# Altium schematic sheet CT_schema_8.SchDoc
size 371 x 336 mm
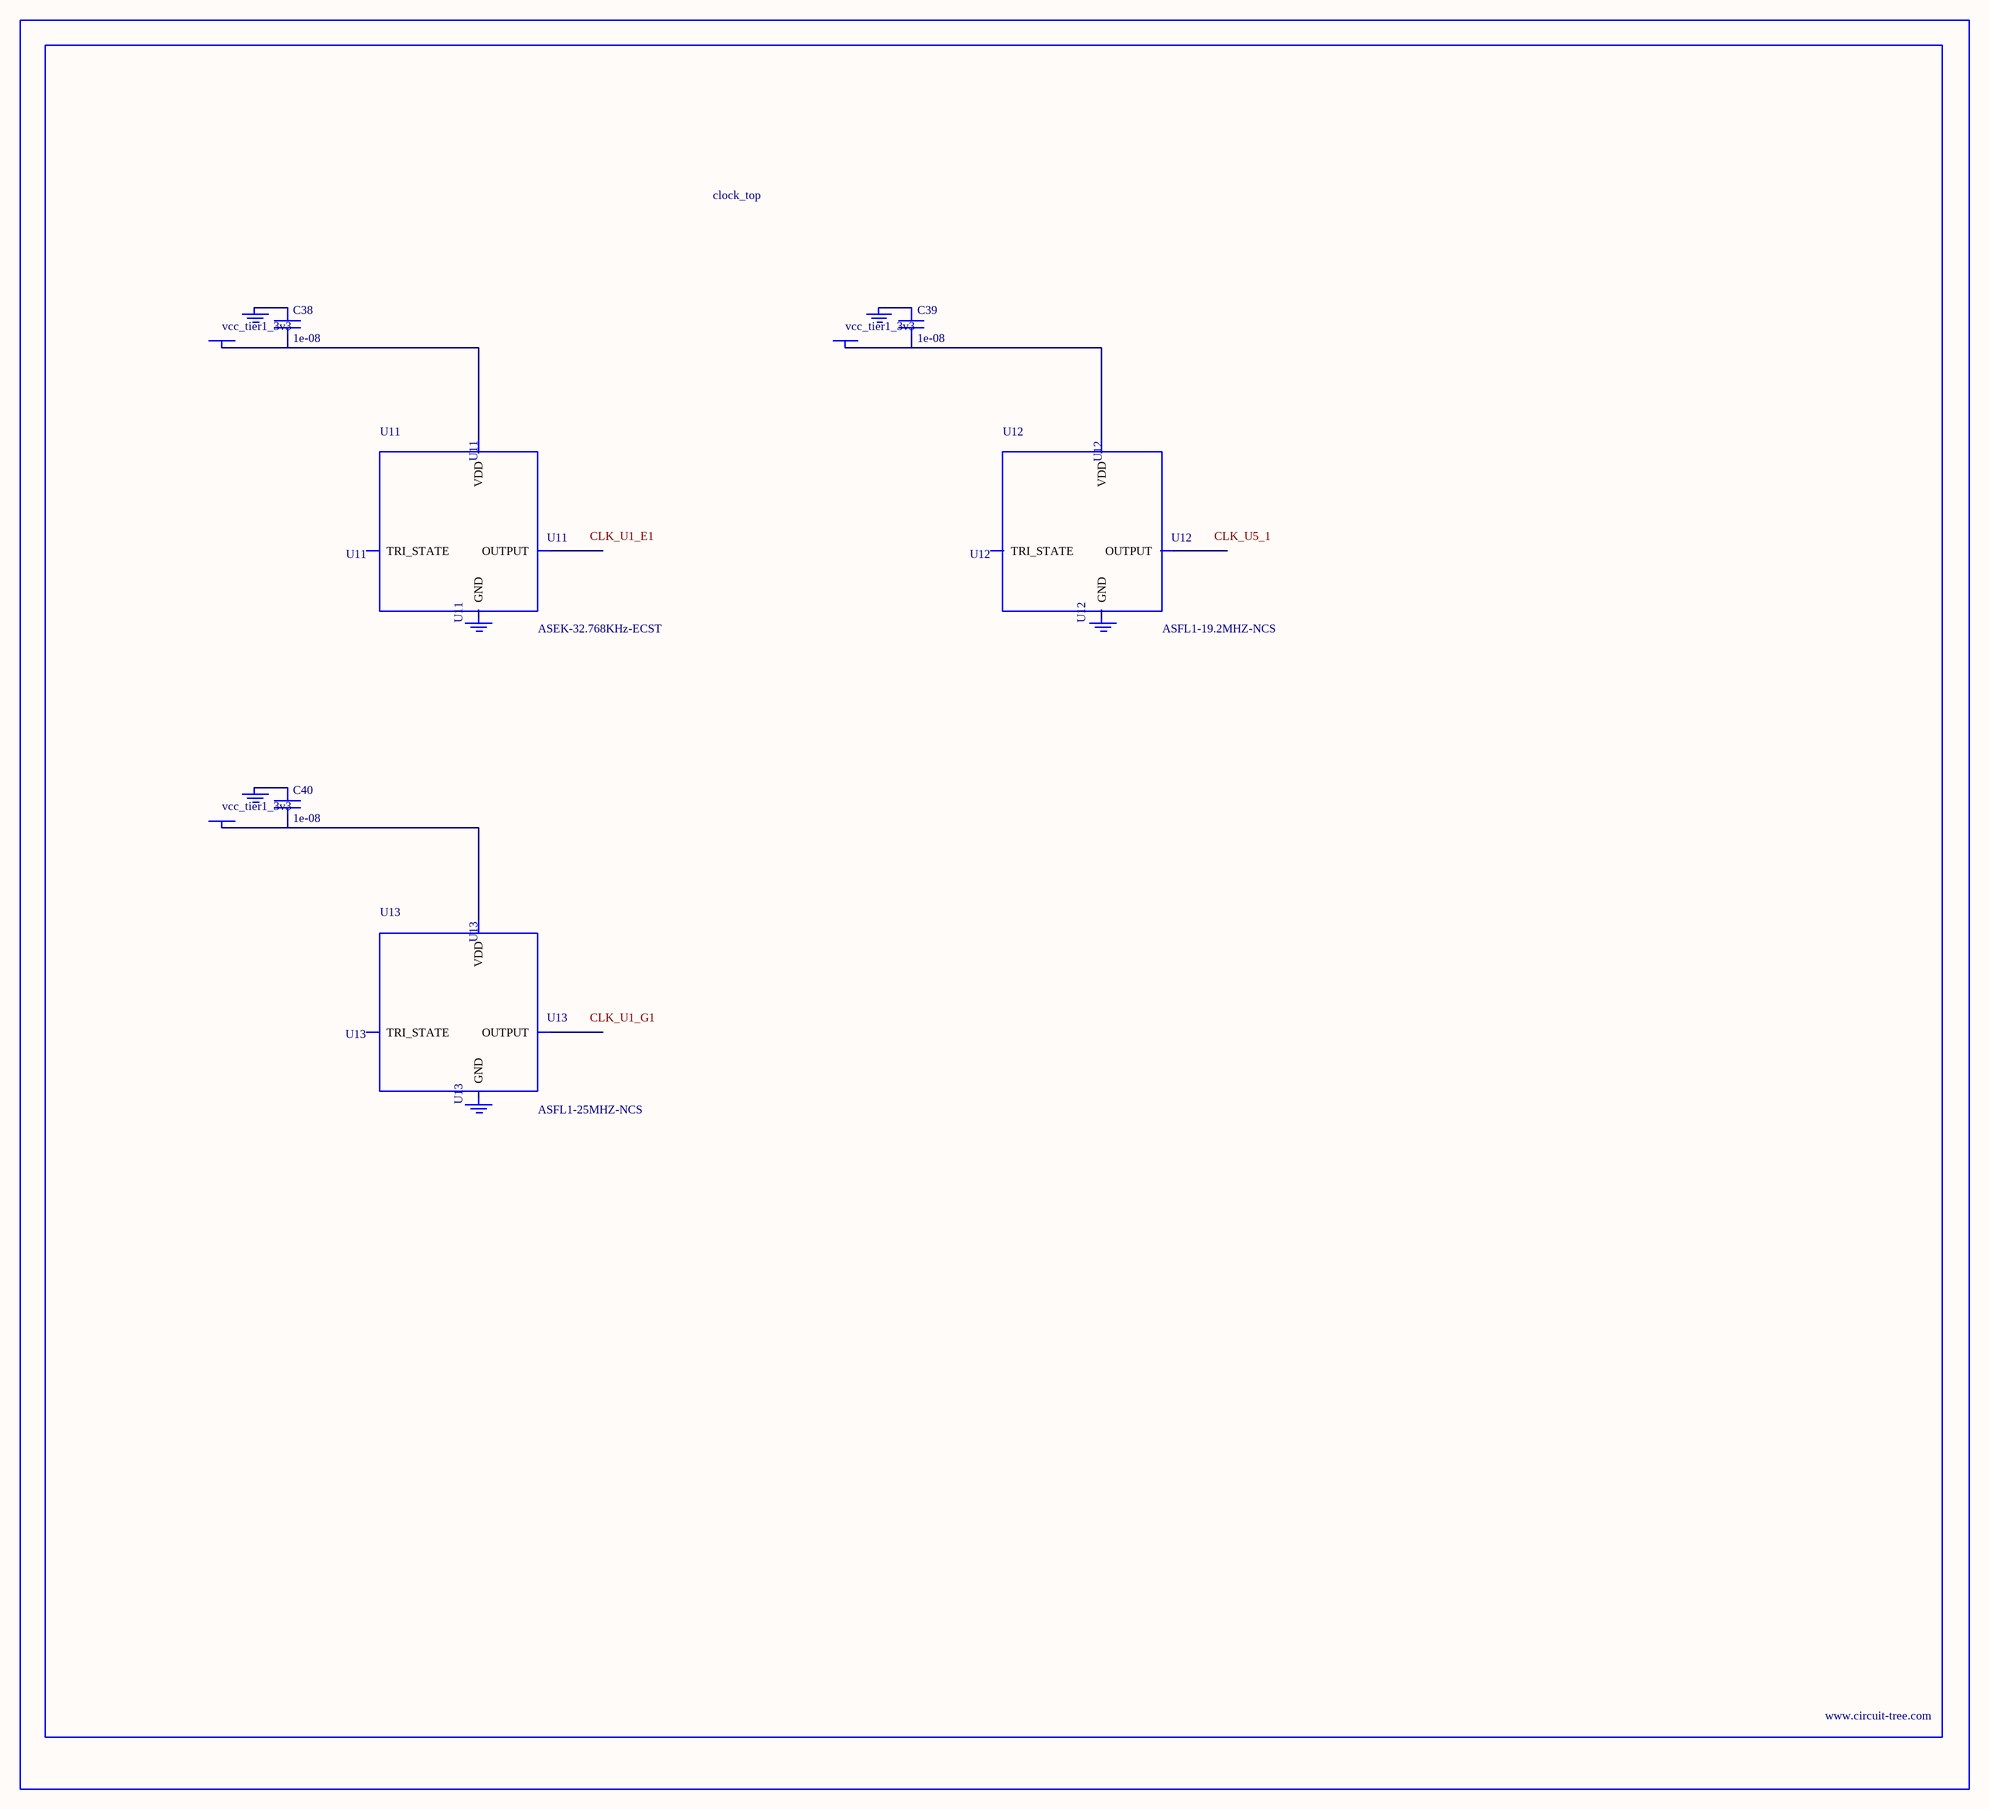
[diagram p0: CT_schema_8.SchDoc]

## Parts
BORDER7  (no value)
C38  1e-08  [C0402]
C39  1e-08  [C0402]
C40  1e-08  [C0402]
GND_INSTANCE_7_0  (no value)
GND_INSTANCE_7_1  (no value)
GND_INSTANCE_7_2  (no value)
GND_INSTANCE_7_3  (no value)
GND_INSTANCE_7_4  (no value)
GND_INSTANCE_7_5  (no value)
POWER_INSTANCE_7_0  vcc_tier1_3v3
POWER_INSTANCE_7_1  vcc_tier1_3v3
POWER_INSTANCE_7_2  vcc_tier1_3v3
U11  ASEK-32.768KHz-ECST  [ASEK]
U12  ASFL1-19.2MHZ-NCS  [ASFL1]
U13  ASFL1-25MHZ-NCS  [ASFL1]

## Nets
NetC38_1: C38.1 GND_INSTANCE_7_0.0(GND)
NetC38_2: C38.2 POWER_INSTANCE_7_0.0(PWR) U11.4(VDD)
NetC39_1: C39.1 GND_INSTANCE_7_2.0(GND)
NetC39_2: C39.2 POWER_INSTANCE_7_1.0(PWR) U12.4(VDD)
NetC40_1: C40.1 GND_INSTANCE_7_4.0(GND)
NetC40_2: C40.2 POWER_INSTANCE_7_2.0(PWR) U13.4(VDD)

Not connected (* = marked no-connect by the designer): GND_INSTANCE_7_1 0(GND); GND_INSTANCE_7_3 0(GND); GND_INSTANCE_7_5 0(GND); U11 1(TRI_STATE) 2(GND) 3(OUTPUT); U12 1(TRI_STATE) 2(GND) 3(OUTPUT); U13 1(TRI_STATE) 2(GND) 3(OUTPUT)

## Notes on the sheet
- Labels drawn without touching a wire or pin: CLK_U1_E1, CLK_U1_G1, CLK_U5_1

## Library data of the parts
BORDER7 = BORDER_PAGE7
C38-C40 = C0402C103K3RAC
GND_INSTANCE_7_0-GND_INSTANCE_7_5 = GND
POWER_INSTANCE_7_0-POWER_INSTANCE_7_2 = PWR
